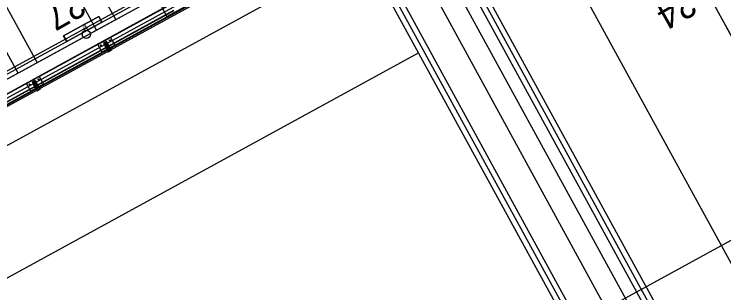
# Model space of a CAD drawing. Extents: x -783978 to -783565, y -1064821 to -1064596.
# Drawn here: x -783741.25 to -783731.52, y -1064675.51 to -1064671.69 of the extents above; entities that cross this region are included whole.
import ezdxf

# ---------------------------------------------------------------- set-up
doc = ezdxf.new("R2010")
doc.units = 0
for name, color, linetype in [('Default', 7, 'Continuous'), ('SO 01_10_01', 7, 'Continuous'), ('SO 01_20_01', 7, 'Continuous'), ('SO 01_50_01', 7, 'Continuous'), ('SO 01_74_01', 7, 'Continuous'), ('SO 01_86_04', 7, 'Continuous')]:
    doc.layers.add(name, color=color, linetype=linetype)

# ---------------------------------------------------------------- blocks, each defined once
blk = doc.blocks.new('POINT_DISPLAY')
at = {"layer": 'Default'}
blk.add_line((0, 0), (0, 0), dxfattribs=at)

msp = doc.modelspace()

# ---------------------------------------------------------------- linework, layer by layer
at = {"layer": 'SO 01_10_01'}
msp.add_lwpolyline([(-783714.1856, -1064665.36), (-783749.2769, -1064684.559)], dxfattribs=at)
at = {"layer": 'SO 01_20_01'}
for p, q in [((-783726.9264, -1064683.3119), (-783738.1468, -1064662.8034)), ((-783733.4514, -1064668.2604), (-783745.2333, -1064674.7064)), ((-783745.0893, -1064674.9696), (-783733.0442, -1064668.3796)), ((-783726.2758, -1064681.3758), (-783733.0626, -1064668.971)), ((-783728.3462, -1064683.4774), (-783735.9297, -1064669.6163)), ((-783728.2804, -1064683.4414), (-783735.8639, -1064669.5803)), ((-783728.2146, -1064683.4054), (-783735.7981, -1064669.5443)), ((-783745.2813, -1064674.6187), (-783736.222, -1064669.6623)), ((-783736.2028, -1064669.6973), (-783745.2621, -1064674.6538)), ((-783729.1709, -1064682.9597), (-783736.2025, -1064670.1075)), ((-783739.8556, -1064671.7642), (-783740.7195, -1064670.1851)), ((-783732.3925, -1064677.9567), (-783736.5753, -1064670.3115)), ((-783740.1188, -1064671.9082), (-783740.9827, -1064670.3291)), ((-783732.5241, -1064678.0287), (-783736.7069, -1064670.3835)), ((-783732.4653, -1064677.9799), (-783736.6411, -1064670.3475)), ((-783728.9074, -1064682.8156), (-783735.6946, -1064670.411)), ((-783736.4011, -1064670.7861), (-783745.288, -1064675.6482)), ((-783740.9346, -1064672.3546), (-783741.7986, -1064670.7754)), ((-783741.1978, -1064672.4985), (-783742.0618, -1064670.9194))]:
    msp.add_line(p, q, dxfattribs=at)
at = {"layer": 'SO 01_50_01'}
msp.add_lwpolyline([(-783783.6289, -1064698.4393), (-783735.7029, -1064672.2185)], dxfattribs=at)
at = {"layer": 'SO 01_74_01'}
for p, q in [((-783744.8433, -1064674.8464), (-783733.0394, -1064668.3884)), ((-783733.0298, -1064668.4059), (-783744.8337, -1064674.8639)), ((-783739.1048, -1064671.5529), (-783741.9076, -1064673.0864)), ((-783739.1018, -1064671.5585), (-783741.9046, -1064673.0919)), ((-783741.8627, -1064673.1686), (-783739.0599, -1064671.6351)), ((-783741.8596, -1064673.1741), (-783739.0569, -1064671.6407)), ((-783739.9792, -1064672.1738), (-783739.9353, -1064672.1498)), ((-783739.9744, -1064672.1825), (-783739.9305, -1064672.1585)), ((-783739.9353, -1064672.1498), (-783739.9161, -1064672.1849)), ((-783739.9305, -1064672.1585), (-783739.9209, -1064672.1761)), ((-783739.96, -1064672.2089), (-783739.9792, -1064672.1738)), ((-783739.9648, -1064672.2001), (-783739.9744, -1064672.1825)), ((-783739.9209, -1064672.1761), (-783739.9648, -1064672.2001)), ((-783739.9161, -1064672.1849), (-783739.96, -1064672.2089)), ((-783740.9573, -1064672.7089), (-783740.9135, -1064672.6849)), ((-783740.9381, -1064672.744), (-783740.9573, -1064672.7089)), ((-783740.9525, -1064672.7177), (-783740.9087, -1064672.6937)), ((-783740.9429, -1064672.7353), (-783740.9525, -1064672.7177)), ((-783740.8991, -1064672.7113), (-783740.9429, -1064672.7353)), ((-783740.8943, -1064672.72), (-783740.9381, -1064672.744)), ((-783740.9135, -1064672.6849), (-783740.8943, -1064672.72)), ((-783740.9087, -1064672.6937), (-783740.8991, -1064672.7113))]:
    msp.add_line(p, q, dxfattribs=at)
for points in [[(-783733.0802, -1064668.3138), (-783745.8491, -1064675.2998)], [(-783739.9916, -1064672.0666), (-783740.0189, -1064672.0815)], [(-783739.9886, -1064672.0721), (-783740.0158, -1064672.087)], [(-783739.9398, -1064672.1415), (-783739.9788, -1064672.0703)], [(-783740.0226, -1064672.0943), (-783739.9837, -1064672.1655)], [(-783740.0171, -1064672.0913), (-783739.9782, -1064672.1625)], [(-783740.0052, -1064672.074), (-783739.9572, -1064672.1618)], [(-783739.9593, -1064672.1059), (-783740.0032, -1064672.1299)], [(-783739.9454, -1064672.1445), (-783739.9843, -1064672.0734)], [(-783739.9739, -1064672.1637), (-783739.9466, -1064672.1488)], [(-783739.9709, -1064672.1692), (-783739.9436, -1064672.1543)], [(-783741.0008, -1064672.6295), (-783740.9619, -1064672.7006)], [(-783740.9698, -1064672.6017), (-783740.997, -1064672.6167)], [(-783740.9953, -1064672.6265), (-783740.9563, -1064672.6976)], [(-783740.9667, -1064672.6073), (-783740.994, -1064672.6222)], [(-783740.9834, -1064672.6092), (-783740.9354, -1064672.6969)], [(-783740.9375, -1064672.6411), (-783740.9813, -1064672.6651)], [(-783740.9235, -1064672.6797), (-783740.9625, -1064672.6085)], [(-783740.918, -1064672.6766), (-783740.9569, -1064672.6055)], [(-783740.9521, -1064672.6989), (-783740.9248, -1064672.6839)], [(-783740.949, -1064672.7044), (-783740.9218, -1064672.6895)]]:
    msp.add_lwpolyline(points, dxfattribs=at)
for points in [[(-783738.8804, -1064671.3902), (-783739.2313, -1064671.5822), (-783739.1545, -1064671.7226), (-783738.8036, -1064671.5306)], [(-783739.8695, -1064672.1138), (-783740.045, -1064672.2098), (-783740.1026, -1064672.1045), (-783739.9271, -1064672.0085)], [(-783740.8477, -1064672.6489), (-783741.0231, -1064672.7449), (-783741.0807, -1064672.6397), (-783740.9053, -1064672.5437)]]:
    msp.add_lwpolyline(points, close=True, dxfattribs=at)
for centre in [(-783739.939, -1064672.0492), (-783740.0618, -1064672.1164), (-783741.04, -1064672.6516), (-783740.9172, -1064672.5844)]:
    msp.add_circle(centre, 0.006, dxfattribs=at)
for centre, radius, start, end in [((-783739.987, -1064672.0749), 0.00945, 28.68349, 118.68349), ((-783739.987, -1064672.0749), 0.00315, 28.68349, 118.68349), ((-783740.0143, -1064672.0898), 0.00945, 118.68349, 208.68349), ((-783740.0143, -1064672.0898), 0.00315, 118.68349, 208.68349), ((-783739.9754, -1064672.1609), 0.00945, 208.68349, 298.68349), ((-783739.9754, -1064672.1609), 0.00315, 208.68349, 298.68349), ((-783739.9481, -1064672.146), 0.00315, 298.68349, 28.68349), ((-783739.9481, -1064672.146), 0.00945, 298.68349, 28.68349), ((-783740.9925, -1064672.625), 0.00945, 118.68349, 208.68349), ((-783740.9925, -1064672.625), 0.00315, 118.68349, 208.68349), ((-783740.9652, -1064672.61), 0.00945, 28.68349, 118.68349), ((-783740.9652, -1064672.61), 0.00315, 28.68349, 118.68349), ((-783740.9536, -1064672.6961), 0.00945, 208.68349, 298.68349), ((-783740.9536, -1064672.6961), 0.00315, 208.68349, 298.68349), ((-783740.9263, -1064672.6812), 0.00315, 298.68349, 28.68349), ((-783740.9263, -1064672.6812), 0.00945, 298.68349, 28.68349)]:
    msp.add_arc(centre, radius, start, end, dxfattribs=at)
at = {"layer": 'SO 01_86_04'}
for p, q in [((-783740.0897, -1064671.7213), (-783740.5722, -1064671.9853)), ((-783740.5722, -1064671.9853), (-783740.0897, -1064671.7213)), ((-783740.5722, -1064671.9853), (-783740.0897, -1064671.7213)), ((-783740.0897, -1064671.7213), (-783740.5722, -1064671.9853)), ((-783740.0465, -1064671.8002), (-783740.0897, -1064671.7213)), ((-783740.0897, -1064671.7213), (-783740.0465, -1064671.8002)), ((-783740.0465, -1064671.8002), (-783740.0897, -1064671.7213)), ((-783740.0897, -1064671.7213), (-783740.0465, -1064671.8002)), ((-783740.529, -1064672.0642), (-783740.0465, -1064671.8002)), ((-783740.0465, -1064671.8002), (-783740.529, -1064672.0642)), ((-783740.529, -1064672.0642), (-783740.0465, -1064671.8002)), ((-783740.0465, -1064671.8002), (-783740.529, -1064672.0642)), ((-783740.5722, -1064671.9853), (-783740.529, -1064672.0642)), ((-783740.529, -1064672.0642), (-783740.5722, -1064671.9853)), ((-783740.5722, -1064671.9853), (-783740.529, -1064672.0642)), ((-783740.529, -1064672.0642), (-783740.5722, -1064671.9853))]:
    msp.add_line(p, q, dxfattribs=at)
for points in [[(-783718.4346, -1064695.4446), (-783718.5614, -1064695.5192), (-783725.2526, -1064683.2773), (-783728.2152, -1064677.831), (-783729.7032, -1064675.1114), (-783731.1911, -1064672.3918), (-783732.679, -1064669.6722), (-783734.1669, -1064666.9527), (-783735.4626, -1064664.5844)], [(-783733.4229, -1064668.3125), (-783737.6471, -1064670.5617), (-783739.9521, -1064671.817), (-783742.6942, -1064673.3169), (-783745.0268, -1064674.6345), (-783745.4136, -1064673.9496)]]:
    msp.add_lwpolyline(points, dxfattribs=at)
msp.add_circle((-783740.2603, -1064671.966), 0.0549, dxfattribs=at)

# ---------------------------------------------------------------- block references
at = {"layer": 'SO 01_86_04', "xscale": 0.010000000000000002, "yscale": 0.009999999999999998, "rotation": 28.683491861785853}
for p in [(-783740.0897, -1064671.7213), (-783740.0897, -1064671.7213), (-783740.3309, -1064671.8533), (-783740.0465, -1064671.8002), (-783740.0465, -1064671.8002), (-783740.5722, -1064671.9853), (-783740.5722, -1064671.9853), (-783740.529, -1064672.0642), (-783740.529, -1064672.0642)]:
    msp.add_blockref('POINT_DISPLAY', p, dxfattribs=at)

# ---------------------------------------------------------------- texts
at = {"layer": 'SO 01_86_04'}
for s, height, rotation, p in [('27', 0.351, 209.46001, (-783740.4012, -1064671.3672)), ('24', 0.351, 209.46001, (-783732.0208, -1064671.3574)), ('4', 0.1, 28.68349, (-783740.2877, -1064671.9322))]:
    msp.add_text(s, height=height, rotation=rotation, dxfattribs=at).set_placement(p)

doc.saveas('drawing.dxf')
